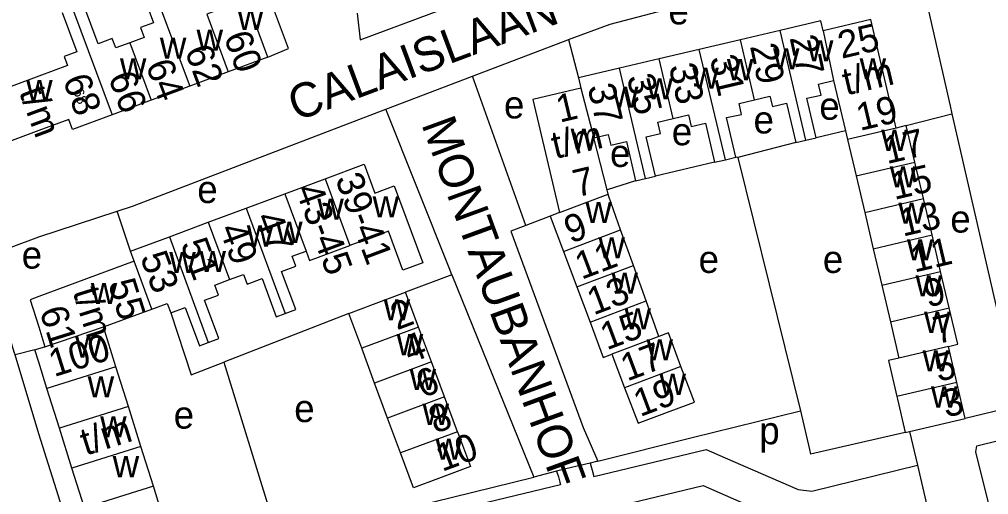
# Model space of a CAD drawing. Extents: x 157768 to 159790, y 387230 to 389604.
# Drawn here: x 159097.2 to 159238.6, y 388653.9 to 388723.2 of the extents above; entities that cross this region are included whole.
import ezdxf

# ---------------------------------------------------------------- set-up
doc = ezdxf.new("R2010")
doc.units = 0
for name, color, linetype in [('BLT_Basislijn', 7, 'Continuous'), ('BLT_Bebouwing', 7, 'Continuous'), ('BLT_Centroide', 7, 'Continuous'), ('BLT_Huisnummer', 7, 'Continuous'), ('BLT_Huisnummer_ tussenligend', 7, 'Continuous'), ('BLT_Huisnummer_reeks', 7, 'Continuous'), ('BLT_Onderverdeling_panden', 7, 'Continuous'), ('BLT_Straatnaam', 7, 'Continuous')]:
    doc.layers.add(name, color=color, linetype=linetype)

msp = doc.modelspace()

# ---------------------------------------------------------------- linework, layer by layer
at = {"layer": 'BLT_Basislijn'}
for p, q in [((159177.3, 388720.26), (159178.75, 388714.66)), ((159150.64, 388710.09), (159163.3, 388714.92)), ((159171.07, 388693.17), (159163.3, 388714.92)), ((159226.56, 388707.71), (159233.22, 388709.41)), ((159201.97, 388703.09), (159201.7, 388703.11)), ((159201.97, 388703.09), (159211.12, 388666.12)), ((159198.59, 388702.37), (159189.97, 388700.35)), ((159187.07, 388699.66), (159182.9, 388698.34)), ((159113.37, 388689.39), (159111.46, 388695.23)), ((159174.6, 388694.52), (159171.07, 388693.17)), ((159160.27, 388685.97), (159153.52, 388683.43)), ((159160.27, 388685.97), (159172.2, 388656.47)), ((159145.22, 388680.34), (159126.99, 388673.24)), ((159099.43, 388675.03), (159096.55, 388674.28)), ((159126.99, 388673.24), (159135.01, 388647.37)), ((159195.33, 388662.25), (159211.12, 388666.12)), ((159242.97, 388666.92), (159235.16, 388665.03)), ((159181.57, 388658.8), (159195.33, 388662.25)), ((159226.41, 388662.97), (159212.58, 388659.82)), ((159227.02, 388663.12), (159228.17, 388658.21)), ((159176.88, 388657.69), (159175.54, 388657.34)), ((159180.43, 388658.53), (159176.88, 388657.69)), ((159181.57, 388658.8), (159180.43, 388658.53)), ((159228.17, 388658.21), (159229.54, 388652.34)), ((159135.01, 388647.37), (159172.2, 388656.47)), ((159175.54, 388657.34), (159172.2, 388656.47))]:
    msp.add_line(p, q, dxfattribs=at)
for points in [[(159146.47, 388724.1), (159146.89, 388720.24), (159179.17, 388732.29), (159199.12, 388737.23)], [(159177.3, 388720.26), (159183.37, 388722.48), (159194.31, 388725.35), (159218.67, 388731.21), (159223.12, 388732.06), (159225.89, 388732.25), (159227.5, 388731.47), (159228.51, 388730.05), (159232.95, 388710.61), (159233.22, 388709.41)], [(159133.4, 388717.7), (159136.44, 388718.96), (159132.62, 388729.1)], [(159163.3, 388714.92), (159177.17, 388720.21), (159177.3, 388720.26)], [(159111.46, 388695.23), (159113.67, 388695.95), (159150.64, 388710.09)], [(159160.27, 388685.97), (159159.85, 388686.99), (159150.64, 388710.09)], [(159233.22, 388709.41), (159242.83, 388667.61), (159242.97, 388666.92)], [(159217.68, 388706.97), (159213.41, 388705.94)], [(159210.44, 388705.24), (159201.97, 388703.09)], [(159096.55, 388674.28), (159096.43, 388674.68), (159093.31, 388685.08), (159093.42, 388687.56), (159093.75, 388688.23), (159095.97, 388690.01), (159100, 388691.52), (159111.46, 388695.23)], [(159171.07, 388693.17), (159168.86, 388692.33), (159179.4, 388663.72), (159181.57, 388658.8)], [(159119.25, 388680.41), (159122.24, 388671.38), (159126.99, 388673.24)], [(159107.16, 388639.28), (159105.72, 388644.78), (159100, 388662.79), (159096.55, 388674.28)], [(159211.12, 388666.12), (159212.42, 388660.51), (159212.58, 388659.82)], [(159253.23, 388593.87), (159236.69, 388660.17), (159236.85, 388661.02), (159243.76, 388662.76)], [(159180.96, 388656.56), (159197.37, 388660.49), (159200.12, 388659.31), (159210.79, 388654.66), (159212.8, 388654.45), (159228.17, 388658.21)], [(159180.43, 388658.53), (159180.74, 388657.51), (159180.96, 388656.56)], [(159175.54, 388657.34), (159175.82, 388656.54), (159176.03, 388655.72), (159176.09, 388655.39)], [(159108.35, 388633.78), (159130.54, 388638.48), (159133.12, 388639.51), (159136.15, 388640.89), (159156.15, 388650.61), (159176.09, 388655.39)], [(159180.98, 388651.42), (159196.92, 388655.24), (159198.13, 388654.72), (159212.55, 388648.43)]]:
    msp.add_lwpolyline(points, dxfattribs=at)
at = {"layer": 'BLT_Bebouwing'}
for p, q in [((159208.15, 388721.59), (159202.35, 388720.22)), ((159202.35, 388720.22), (159196.36, 388718.81)), ((159196.36, 388718.81), (159190.51, 388717.43)), ((159133.4, 388717.7), (159127.65, 388715.56)), ((159190.51, 388717.43), (159184.74, 388716.08)), ((159127.65, 388715.56), (159122.03, 388713.48)), ((159184.74, 388716.08), (159178.75, 388714.66)), ((159178.75, 388714.66), (159179.1, 388713.17)), ((159215.96, 388714.28), (159217.68, 388706.97)), ((159122.03, 388713.48), (159116.42, 388711.4)), ((159116.42, 388711.4), (159110.7, 388709.28)), ((159226.56, 388707.71), (159225.1, 388707.36)), ((159227.81, 388702.4), (159226.56, 388707.71)), ((159182.9, 388698.34), (159181, 388705.94)), ((159217.68, 388706.97), (159217.99, 388705.69)), ((159217.99, 388705.69), (159219.24, 388700.38)), ((159229.06, 388697.09), (159227.81, 388702.4)), ((159135.89, 388697.77), (159141.77, 388699.96)), ((159219.24, 388700.38), (159220.49, 388695.07)), ((159130.26, 388695.68), (159135.89, 388697.77)), ((159183.05, 388697.7), (159182.9, 388698.34)), ((159230.31, 388691.78), (159229.06, 388697.09)), ((159124.74, 388693.62), (159130.26, 388695.68)), ((159175.97, 388695.04), (159174.6, 388694.52)), ((159174.6, 388694.52), (159176.54, 388689.37)), ((159220.49, 388695.07), (159221.74, 388689.75)), ((159119.06, 388691.51), (159124.74, 388693.62)), ((159113.37, 388689.39), (159119.06, 388691.51)), ((159186.75, 388687.34), (159184.88, 388692.52)), ((159231.57, 388686.46), (159230.31, 388691.78)), ((159113.9, 388687.97), (159113.37, 388689.39)), ((159176.54, 388689.37), (159178.48, 388684.22)), ((159221.74, 388689.75), (159222.99, 388684.44)), ((159188.61, 388682.16), (159186.75, 388687.34)), ((159232.82, 388681.15), (159231.57, 388686.46)), ((159222.99, 388684.44), (159224.24, 388679.13)), ((159155.42, 388678.35), (159153.52, 388683.43)), ((159178.48, 388684.22), (159180.42, 388679.08)), ((159190.48, 388676.99), (159188.61, 388682.16)), ((159109.44, 388678.38), (159116.5, 388680.98)), ((159147.11, 388675.26), (159145.22, 388680.34)), ((159224.24, 388679.13), (159225.49, 388673.82)), ((159100.91, 388675.49), (159109.44, 388678.38)), ((159111.26, 388672.57), (159109.44, 388678.38)), ((159157.31, 388673.27), (159155.42, 388678.35)), ((159191.85, 388677.5), (159190.48, 388676.99)), ((159193.69, 388672.61), (159191.85, 388677.5)), ((159149, 388670.17), (159147.11, 388675.26)), ((159233.92, 388670.27), (159232.69, 388675.52)), ((159159.2, 388668.18), (159157.31, 388673.27)), ((159183.62, 388674.4), (159185.47, 388669.51)), ((159225.49, 388673.82), (159223.94, 388673.46)), ((159223.94, 388673.46), (159225.18, 388668.22)), ((159113.09, 388666.76), (159111.26, 388672.57)), ((159235.16, 388665.03), (159233.92, 388670.27)), ((159103.02, 388663.6), (159101.2, 388669.42)), ((159150.9, 388665.09), (159149, 388670.17)), ((159161.1, 388663.1), (159159.2, 388668.18)), ((159114.91, 388660.95), (159113.09, 388666.76)), ((159152.79, 388660.01), (159150.9, 388665.09)), ((159227.02, 388663.12), (159235.16, 388665.03)), ((159104.84, 388657.79), (159103.02, 388663.6)), ((159226.41, 388662.97), (159227.02, 388663.12)), ((159116.73, 388655.14), (159114.91, 388660.95)), ((159106.66, 388651.98), (159104.84, 388657.79)), ((159118.55, 388649.33), (159116.73, 388655.14))]:
    msp.add_line(p, q, dxfattribs=at)
for points in [[(159114.63, 388728.36), (159116.73, 388722.7), (159114.84, 388722), (159115.38, 388720.56), (159113.31, 388719.8)], [(159133.4, 388717.7), (159129.75, 388727.56), (159126.05, 388726.18), (159126.59, 388724.72), (159124.54, 388723.96)], [(159113.31, 388719.8), (159111.24, 388719.03), (159110.73, 388720.41), (159108.66, 388719.62), (159106.53, 388725.37)], [(159103.41, 388724.21), (159105.54, 388718.48), (159103.73, 388717.8), (159104.21, 388716.49), (159100, 388714.93), (159093.45, 388712.5), (159091.39, 388715.41)], [(159214.42, 388721.55), (159214.08, 388722.99), (159208.15, 388721.59)], [(159225.1, 388707.36), (159221.37, 388723.19), (159214.42, 388721.55)], [(159213.41, 388705.94), (159212.05, 388711.7), (159214.15, 388712.16), (159213.77, 388713.77), (159215.96, 388714.28)], [(159179.1, 388713.17), (159172.09, 388711.52), (159175.97, 388695.04)], [(159201.7, 388703.11), (159200.33, 388708.9), (159202.54, 388709.31), (159202.16, 388710.95), (159204.41, 388711.48)], [(159204.41, 388711.48), (159206.66, 388712.01), (159207.02, 388710.48), (159209.09, 388710.97), (159210.44, 388705.24)], [(159110.7, 388709.28), (159104.94, 388707.14), (159104.4, 388708.62), (159100, 388706.99), (159090.65, 388703.52), (159085.3, 388711.11)], [(159189.97, 388700.35), (159188.62, 388706.07), (159190.72, 388706.56), (159190.33, 388708.23), (159192.55, 388708.75)], [(159192.55, 388708.75), (159194.77, 388709.28), (159195.17, 388707.58), (159197.25, 388708.07), (159198.59, 388702.37)], [(159181, 388705.94), (159183.07, 388706.43), (159183.45, 388704.84), (159185.72, 388705.38), (159187.07, 388699.66)], [(159210.44, 388705.24), (159211.88, 388705.58)], [(159211.88, 388705.58), (159213.41, 388705.94)], [(159198.59, 388702.37), (159200.2, 388702.75)], [(159200.2, 388702.75), (159201.7, 388703.11)], [(159141.77, 388699.96), (159147.45, 388702.08), (159149.01, 388697.89), (159151.84, 388698.94), (159156.02, 388687.71), (159153.13, 388686.63), (159151.01, 388692.31), (159145.4, 388690.22)], [(159187.07, 388699.66), (159188.5, 388700)], [(159188.5, 388700), (159189.97, 388700.35)], [(159184.88, 388692.52), (159183.14, 388697.36), (159183.05, 388697.7)], [(159139, 388689.43), (159139.52, 388688.03), (159145.4, 388690.22)], [(159135.97, 388680.32), (159137.5, 388680.89), (159135.43, 388686.46), (159137.52, 388687.25), (159136.98, 388688.68), (159139, 388689.43)], [(159113.9, 388687.97), (159100, 388682.79), (159098.77, 388682.33), (159100, 388678.4), (159100.91, 388675.49)], [(159127.85, 388685.27), (159129.88, 388686.02), (159130.41, 388684.6), (159132.58, 388685.41), (159134.66, 388679.83), (159135.97, 388680.32)], [(159124.73, 388676.09), (159126.29, 388676.67), (159124.2, 388682.28), (159126.23, 388683.01), (159125.69, 388684.46), (159127.85, 388685.27)], [(159145.22, 388680.34), (159148.84, 388681.69), (159153.52, 388683.43)], [(159116.5, 388680.98), (159118.73, 388681.8), (159119.25, 388680.41)], [(159119.25, 388680.41), (159121.36, 388681.19), (159123.44, 388675.61), (159124.73, 388676.09)], [(159232.69, 388675.52), (159234.07, 388675.84), (159232.82, 388681.15)], [(159180.42, 388679.08), (159182.36, 388673.93), (159183.62, 388674.4)], [(159099.43, 388675.03), (159100, 388675.21), (159100.91, 388675.49)], [(159101.2, 388669.42), (159100, 388673.23), (159099.43, 388675.03)], [(159185.47, 388669.51), (159187.42, 388664.32), (159192.1, 388666.08), (159195.65, 388667.42), (159193.69, 388672.61)], [(159225.18, 388668.22), (159225.27, 388667.84), (159226.41, 388662.97)], [(159161.1, 388663.1), (159162.99, 388658.02), (159158.3, 388656.27), (159154.68, 388654.93), (159152.79, 388660.01)]]:
    msp.add_lwpolyline(points, dxfattribs=at)
at = {"layer": 'BLT_Onderverdeling_panden'}
for p, q in [((159116.25, 388728.96), (159122.03, 388713.48)), ((159104.95, 388724.78), (159110.7, 388709.28)), ((159124.54, 388723.96), (159127.65, 388715.56)), ((159211.88, 388705.58), (159208.15, 388721.59)), ((159214.42, 388721.55), (159215.96, 388714.28)), ((159113.31, 388719.8), (159116.42, 388711.4)), ((159204.41, 388711.48), (159202.35, 388720.22)), ((159200.2, 388702.75), (159196.36, 388718.81)), ((159192.55, 388708.75), (159190.51, 388717.43)), ((159188.5, 388700), (159184.74, 388716.08)), ((159179.1, 388713.17), (159181, 388705.94)), ((159225.1, 388707.36), (159217.99, 388705.69)), ((159219.24, 388700.38), (159227.81, 388702.4)), ((159141.77, 388699.96), (159145.4, 388690.22)), ((159135.89, 388697.77), (159139, 388689.43)), ((159175.97, 388695.04), (159183.05, 388697.7)), ((159220.49, 388695.07), (159229.06, 388697.09)), ((159130.26, 388695.68), (159135.97, 388680.32)), ((159124.74, 388693.62), (159127.85, 388685.27)), ((159119.06, 388691.51), (159124.73, 388676.09)), ((159176.54, 388689.37), (159184.88, 388692.52)), ((159221.74, 388689.75), (159230.31, 388691.78)), ((159116.5, 388680.98), (159113.9, 388687.97)), ((159178.48, 388684.22), (159186.75, 388687.34)), ((159222.99, 388684.44), (159231.57, 388686.46)), ((159180.42, 388679.08), (159188.61, 388682.16)), ((159224.24, 388679.13), (159232.82, 388681.15)), ((159155.42, 388678.35), (159147.11, 388675.26)), ((159190.48, 388676.99), (159183.62, 388674.4)), ((159232.69, 388675.52), (159225.49, 388673.82)), ((159157.31, 388673.27), (159149, 388670.17)), ((159111.26, 388672.57), (159101.2, 388669.42)), ((159193.69, 388672.61), (159185.47, 388669.51)), ((159233.92, 388670.27), (159225.18, 388668.22)), ((159159.2, 388668.18), (159150.9, 388665.09)), ((159113.09, 388666.76), (159103.02, 388663.6)), ((159161.1, 388663.1), (159152.79, 388660.01)), ((159114.91, 388660.95), (159104.84, 388657.79)), ((159116.73, 388655.14), (159106.66, 388651.98))]:
    msp.add_line(p, q, dxfattribs=at)

# ---------------------------------------------------------------- texts
at = {"layer": 'BLT_Centroide'}
for s, p in [('e', (159191.86, 388722.47)), ('w', (159128.97, 388721.67)), ('w', (159123.02, 388718.62)), ('w', (159117.67, 388717.45)), ('w', (159212.06, 388717.09)), ('w', (159207.11, 388715.92)), ('w', (159111.84, 388714.47)), ('w', (159200.39, 388714.33)), ('w', (159219.75, 388714.45)), ('w', (159195.34, 388713.09)), ('w', (159098.17, 388711.31)), ('w', (159188.64, 388711.55)), ('w', (159183.62, 388710.34)), ('e', (159167.87, 388708.76)), ('e', (159213.87, 388708.57)), ('e', (159204.27, 388706.57)), ('w', (159177.58, 388704.22)), ('e', (159192.35, 388704.85)), ('w', (159222.9, 388704.03)), ('e', (159183.34, 388701.69)), ('w', (159224.15, 388698.72)), ('e', (159123.13, 388696.43)), ('w', (159148.7, 388694.34)), ('w', (159140.64, 388694)), ('w', (159179.74, 388693.53)), ('w', (159225.4, 388693.41)), ('e', (159232.98, 388692.12)), ('w', (159130.36, 388690.09)), ('w', (159134.62, 388690.62)), ('w', (159181.65, 388688.38)), ('w', (159226.65, 388688.09)), ('e', (159097.52, 388686.87)), ('w', (159119.05, 388686.22)), ('w', (159123.45, 388686.36)), ('e', (159196.26, 388686.24)), ('e', (159214.38, 388686.24)), ('w', (159183.55, 388683.22)), ('w', (159227.9, 388682.81)), ('w', (159107.59, 388681.72)), ('w', (159150.32, 388679.34)), ('w', (159185.45, 388678.03)), ('w', (159229.15, 388677.5)), ('w', (159152.21, 388674.25)), ('w', (159105.32, 388673.91)), ('w', (159188.66, 388673.5)), ('w', (159228.93, 388671.88)), ('w', (159154.1, 388669.19)), ('w', (159107.14, 388668.09)), ('w', (159190.55, 388668.47)), ('w', (159230.16, 388666.62)), ('e', (159137.27, 388664.5)), ('e', (159119.69, 388663.55)), ('w', (159155.99, 388664.09)), ('w', (159108.96, 388662.28)), ('p', (159205.11, 388661.27)), ('w', (159157.89, 388659)), ('w', (159110.79, 388656.47))]:
    msp.add_text(s, height=4, dxfattribs=at).set_placement(p)
at = {"layer": 'BLT_Huisnummer'}
for s, height, rotation, p in [('60', 4, 290.349, (159126.94, 388720.67)), ('27', 4, 282.0059, (159209.52, 388720.53)), ('64', 4, 290.349, (159115.56, 388716.55)), ('31', 4, 283.2599, (159197.85, 388717.55)), ('68', 1.5, 290.349, (159105.01, 388712.77)), ('37', 4, 283.2442, (159180.03, 388713.38)), ('17', 4, 13.2613, (159223.73, 388702.09)), ('47', 4, 290.406, (159131.52, 388694.34)), ('9', 4, 20.6516, (159177.59, 388690.49)), ('11', 4, 13.2613, (159227.74, 388686.28)), ('53', 4, 290.4139, (159114.75, 388688.54)), ('13', 4, 20.6495, (159180.94, 388680.04)), ('2', 4, 20.4365, (159152.25, 388677.86)), ('7', 4, 13.2613, (159231.02, 388675.84)), ('6', 4, 20.4305, (159155.97, 388667.97)), ('19', 4, 20.6566, (159187.72, 388665.22)), ('3', 4, 13.2613, (159232.32, 388665.14)), ('10', 4, 20.4394, (159158.84, 388657.23))]:
    msp.add_text(s, height=height, rotation=rotation, dxfattribs=at).set_placement(p)
at = {"layer": 'BLT_Huisnummer_ tussenligend'}
for s, rotation, p in [('62', 290.349, (159121.25, 388718.65)), ('29', 282.0059, (159203.74, 388719.3)), ('66', 290.349, (159110.09, 388714.79)), ('33', 283.2599, (159191.88, 388716.34)), ('35', 283.2599, (159185.76, 388714.8)), ('15', 13.2613, (159224.81, 388696.87)), ('13', 13.2613, (159226.06, 388691.52)), ('49', 290.406, (159126.28, 388692.67)), ('51', 290.406, (159120.63, 388690.46)), ('11', 20.6516, (159179.18, 388685.23)), ('9', 13.2613, (159229.66, 388681.19)), ('15', 20.6495, (159182.86, 388674.94)), ('4', 20.4365, (159154.1, 388673.03)), ('17', 20.6495, (159185.83, 388670.4)), ('5', 13.2613, (159231.2, 388670.36)), ('8', 20.4305, (159157.83, 388662.78))]:
    msp.add_text(s, height=4, rotation=rotation, dxfattribs=at).set_placement(p)
at = {"layer": 'BLT_Huisnummer_reeks'}
for s, rotation, p in [('25', 13.2549, (159217.11, 388717.44)), ('t/m', 13.2549, (159217.79, 388712.1)), ('68', 290.3495, (159103.46, 388714.4)), ('t/m', 290.3495, (159097.08, 388712.63)), ('1', 13.2583, (159175.99, 388708.13)), ('19', 13.2549, (159219.79, 388706.93)), ('t/m', 13.2583, (159175.33, 388702.84)), ('7', 13.2583, (159178.47, 388697.25)), ('39-41', 290.406, (159143.21, 388699.97)), ('43-45', 290.406, (159137.39, 388698.41)), ('t/m', 287.4286, (159104.93, 388683.52)), ('55', 287.4292, (159110.09, 388684.72)), ('61', 287.4292, (159100.08, 388680.74)), ('100', 17.4237, (159102.23, 388671.04)), ('t/m', 17.4237, (159106.84, 388659.59))]:
    msp.add_text(s, height=4, rotation=rotation, dxfattribs=at).set_placement(p)
at = {"layer": 'BLT_Straatnaam'}
for s, height, rotation, p in [('CALAISLAAN', 5, 20.5058, (159137.56, 388708.3)), ('MONTAUBANHOF', 4.9999, 290.0218, (159155.78, 388707.93))]:
    msp.add_text(s, height=height, rotation=rotation, dxfattribs=at).set_placement(p)

doc.saveas('drawing.dxf')
